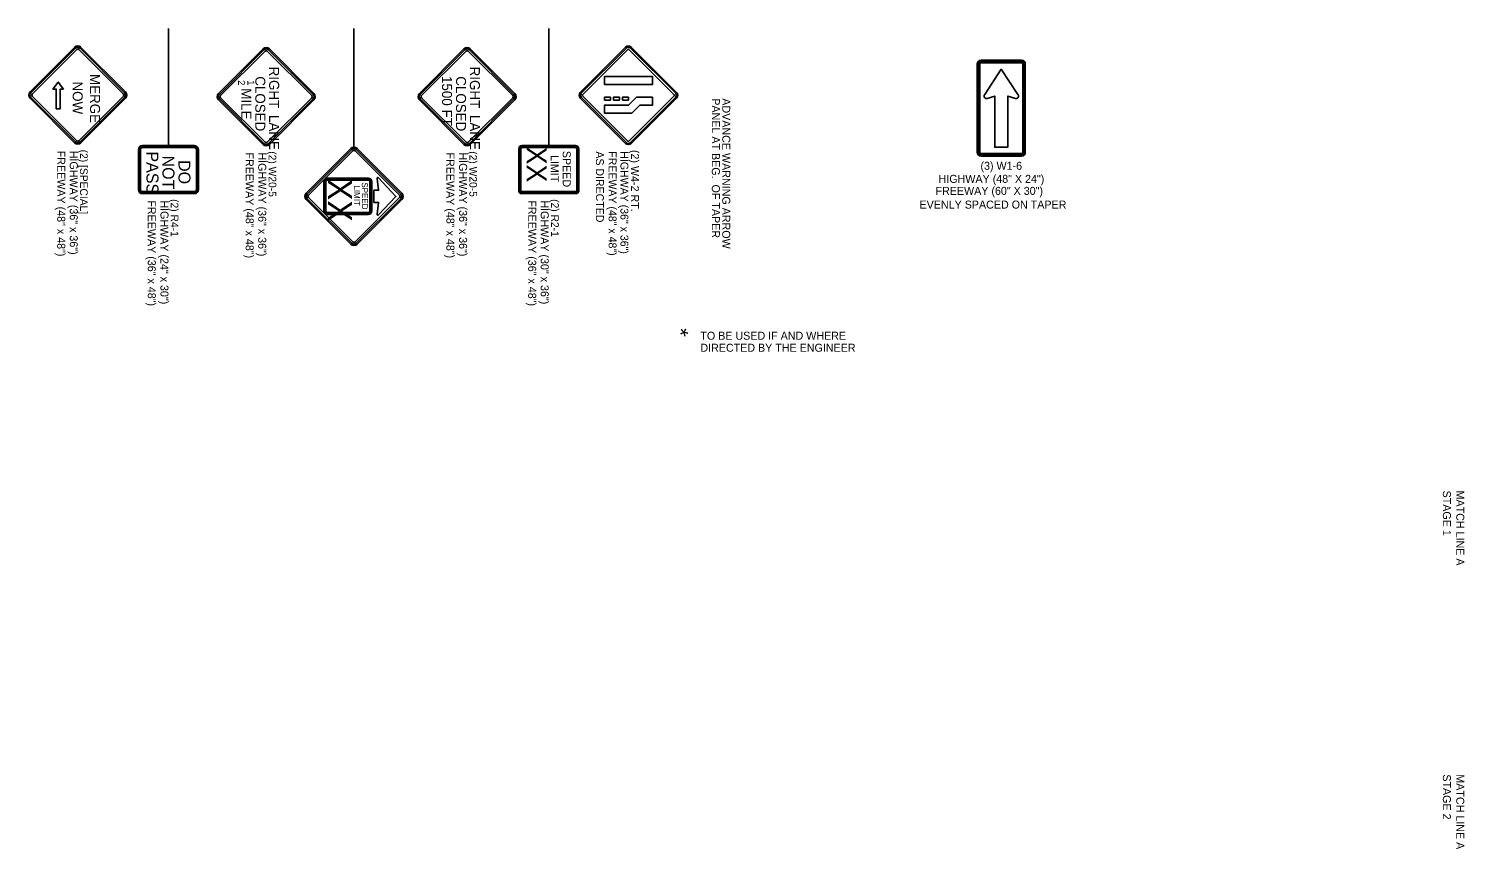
# Model space of a CAD drawing. Extents: x 1930579 to 1937521, y 596183 to 597566.
# Drawn here: x 1934037 to 1935114, y 596519 to 597134 of the extents above; entities that cross this region are included whole.
import ezdxf

# ---------------------------------------------------------------- set-up
doc = ezdxf.new("R2010")
doc.units = 0
for name, color, linetype in [('Default', 7, 'Continuous'), ('P_TC_Signs_Permanent', 7, 'Continuous'), ('P_TC_Signs_Temporary', 7, 'Continuous'), ('R_Annotation', 7, 'Continuous'), ('R_MOT', 7, 'Continuous')]:
    doc.layers.add(name, color=color, linetype=linetype)

msp = doc.modelspace()

# ---------------------------------------------------------------- linework, layer by layer
at = {"layer": 'P_TC_Signs_Permanent'}
for p, q in [((1934450.9, 597086.1), (1934484.8, 597120.1)), ((1934748.5, 597107.5), (1934748.5, 597041.1)), ((1934749.2, 597107.5), (1934749.2, 597041.1)), ((1934750.4, 597107.5), (1934750.4, 597041.1)), ((1934781.7, 597110.3), (1934751.3, 597110.3)), ((1934781.7, 597109.5), (1934751.3, 597109.5)), ((1934781.7, 597108.4), (1934751.3, 597108.4)), ((1934782.6, 597041.1), (1934782.6, 597107.5)), ((1934783.7, 597041.1), (1934783.7, 597107.5)), ((1934784.5, 597041.1), (1934784.5, 597107.5)), ((1934504.9, 597092), (1934504.9, 597098)), ((1934484.8, 597047.9), (1934450.9, 597081.9)), ((1934523, 597081.9), (1934489, 597047.9)), ((1934119.6, 597043.2), (1934119.6, 597013.2)), ((1934120.2, 597043.2), (1934120.2, 597013.2)), ((1934121.1, 597043.2), (1934121.1, 597013.2)), ((1934161.6, 597046.2), (1934122.6, 597046.2)), ((1934161.6, 597045.6), (1934122.6, 597045.6)), ((1934161.6, 597044.7), (1934122.6, 597044.7)), ((1934163.1, 597013.2), (1934163.1, 597043.2)), ((1934164, 597013.2), (1934164, 597043.2)), ((1934164.6, 597013.2), (1934164.6, 597043.2)), ((1934278.8, 597044), (1934245.4, 597010.6)), ((1934279.5, 597043.3), (1934246.1, 597009.9)), ((1934316.3, 597009.9), (1934282.9, 597043.3)), ((1934317, 597010.6), (1934283.6, 597044)), ((1934404.7, 597043.9), (1934404.7, 597012.4)), ((1934405.3, 597043.9), (1934405.3, 597012.4)), ((1934406.2, 597043.9), (1934406.2, 597012.4)), ((1934447.5, 597046.2), (1934407, 597046.2)), ((1934447.5, 597045.6), (1934407, 597045.6)), ((1934447.5, 597044.7), (1934407, 597044.7)), ((1934448.2, 597012.4), (1934448.2, 597043.9)), ((1934449.2, 597012.4), (1934449.2, 597043.9)), ((1934449.7, 597012.4), (1934449.7, 597043.9)), ((1934280.4, 597042.4), (1934247, 597009)), ((1934315.4, 597009), (1934282, 597042.4)), ((1934751.3, 597040.2), (1934781.7, 597040.2)), ((1934751.3, 597039), (1934781.7, 597039)), ((1934751.3, 597038.3), (1934781.7, 597038.3)), ((1934261, 597021.7), (1934292.2, 597021.7)), ((1934122.6, 597011.7), (1934161.6, 597011.7)), ((1934122.6, 597010.8), (1934161.6, 597010.8)), ((1934258.6, 596997.1), (1934258.6, 597019.3)), ((1934294.6, 597019.3), (1934294.6, 596997.1)), ((1934407, 597011.7), (1934447.5, 597011.7)), ((1934407, 597010.8), (1934447.5, 597010.8)), ((1934122.6, 597010.2), (1934161.6, 597010.2)), ((1934245.4, 597005.8), (1934278.8, 596972.4)), ((1934246.1, 597006.4), (1934279.5, 596973)), ((1934247, 597007.4), (1934280.4, 596974)), ((1934282, 596974), (1934315.4, 597007.4)), ((1934282.9, 596973), (1934316.3, 597006.4)), ((1934283.6, 596972.4), (1934317, 597005.8)), ((1934407, 597010.2), (1934447.5, 597010.2)), ((1934292.2, 596994.7), (1934261, 596994.7))]:
    msp.add_line(p, q, dxfattribs=at)
for points in [[(1934485.4, 597119.4), (1934451.5, 597085.5)], [(1934452.6, 597084.4), (1934486.5, 597118.4)], [(1934487.3, 597118.4), (1934521.3, 597084.4)], [(1934522.4, 597085.5), (1934488.4, 597119.4)], [(1934489, 597120.1), (1934506, 597103.1), (1934523, 597086.1)], [(1934778.9, 597084.5), (1934766.5, 597103.5), (1934754.1, 597084.5)], [(1934451.5, 597082.5), (1934485.4, 597048.6)], [(1934486.5, 597049.6), (1934452.6, 597083.6)], [(1934521.3, 597083.6), (1934487.3, 597049.6)], [(1934488.4, 597048.6), (1934522.4, 597082.5)], [(1934755.9, 597081.6), (1934761.6, 597083.3), (1934761.6, 597045), (1934771.4, 597045), (1934771.4, 597083.3), (1934777.1, 597081.6)], [(1934298.5, 597021.6), (1934299.7, 597012.7), (1934296.1, 597012.7), (1934296.1, 597003.7), (1934299.7, 597003.7), (1934298.5, 596994.8)], [(1934299.5, 596994.3), (1934312.6, 597008.2), (1934299.5, 597022.1)], [(1934259.2, 597019.3), (1934259.2, 596997.1)], [(1934260.1, 596997.1), (1934260.1, 597019.3)], [(1934292.2, 597021.1), (1934261, 597021.1)], [(1934261, 597020.2), (1934292.2, 597020.2)], [(1934293.1, 597019.3), (1934293.1, 597008.2), (1934293.1, 596997.1)], [(1934294, 596997.1), (1934294, 597008.2), (1934294, 597019.3)], [(1934292.2, 596996.2), (1934261, 596996.2)], [(1934261, 596995.3), (1934292.2, 596995.3)]]:
    msp.add_lwpolyline(points, dxfattribs=at)
for points in [[(1934468.9, 597092), (1934468.9, 597098), (1934504.9, 597098), (1934504.9, 597092)], [(1934468.9, 597080.4), (1934468.9, 597082.5), (1934473.4, 597082.5), (1934473.4, 597080.4)], [(1934468.9, 597070.5), (1934468.9, 597076.5), (1934486.9, 597076.5), (1934492.9, 597082.5), (1934504.9, 597082.5), (1934504.9, 597076.5), (1934495.4, 597076.5), (1934489.4, 597070.5)], [(1934475.7, 597080.4), (1934475.7, 597082.5), (1934480.2, 597082.5), (1934480.2, 597080.4)], [(1934482.4, 597080.4), (1934482.4, 597082.5), (1934486.9, 597082.5), (1934486.9, 597080.4)]]:
    msp.add_lwpolyline(points, close=True, dxfattribs=at)
for centre, radius, start, end in [((1934486.9, 597117.9), 3, 45, 135), ((1934486.9, 597117.9), 2.1, 45, 135), ((1934486.9, 597117.9), 0.6, 45, 135), ((1934751.3, 597107.5), 2.81, 90, 180), ((1934751.3, 597107.5), 2.06, 90, 180), ((1934751.3, 597107.5), 0.938, 90, 180), ((1934781.7, 597107.5), 2.81, 360, 90), ((1934781.7, 597107.5), 2.06, 360, 90), ((1934781.7, 597107.5), 0.938, 360, 90), ((1934453, 597084), 3, 135, 225), ((1934520.9, 597084), 3, 315, 45), ((1934453, 597084), 2.1, 135, 225), ((1934453, 597084), 0.6, 135, 225), ((1934520.9, 597084), 0.6, 315, 45), ((1934520.9, 597084), 2.1, 315, 45), ((1934755.4, 597083.3), 1.76, 146.5994, 285.9691), ((1934691.3, 597125.5), 75, 326.5994, 326.857), ((1934777.6, 597083.3), 1.8, 254.0309, 33.4755), ((1934841.7, 597125.6), 75, 213.2286, 213.4755), ((1934122.6, 597043.2), 3, 90, 180), ((1934122.6, 597043.2), 2.4, 90, 180), ((1934122.6, 597043.2), 1.5, 90, 180), ((1934161.6, 597043.2), 3, 360, 90), ((1934161.6, 597043.2), 2.4, 360, 90), ((1934161.6, 597043.2), 1.5, 360, 90), ((1934281.2, 597041.6), 3.38, 45, 135), ((1934281.2, 597041.6), 2.44, 45, 135), ((1934281.2, 597041.6), 1.13, 45, 135), ((1934407, 597043.9), 2.25, 90, 180), ((1934407, 597043.9), 1.69, 90, 180), ((1934407, 597043.9), 0.75, 90, 180), ((1934447.5, 597043.9), 2.25, 360, 90), ((1934447.5, 597043.9), 1.69, 360, 90), ((1934447.5, 597043.9), 0.75, 360, 90), ((1934486.9, 597050), 3, 225, 315), ((1934486.9, 597050), 2.1, 225, 315), ((1934486.9, 597050), 0.6, 225, 315), ((1934751.3, 597041.1), 2.81, 180, 270), ((1934751.3, 597041.1), 2.06, 180, 270), ((1934751.3, 597041.1), 0.937, 180, 270), ((1934781.7, 597041.1), 2.81, 270, 360), ((1934781.7, 597041.1), 2.06, 270, 360), ((1934781.7, 597041.1), 0.938, 270, 360), ((1934261, 597019.3), 2.4, 90, 180), ((1934292.2, 597019.3), 2.4, 0, 90), ((1934299.1, 597021.7), 0.563, 43.3117, 187.125), ((1934122.6, 597013.2), 3, 180, 270), ((1934122.6, 597013.2), 2.4, 180, 270), ((1934122.6, 597013.2), 1.5, 180, 270), ((1934161.6, 597013.2), 3, 270, 360), ((1934161.6, 597013.2), 2.4, 270, 360), ((1934161.6, 597013.2), 1.5, 270, 360), ((1934247.8, 597008.2), 3.38, 135, 225), ((1934261, 597019.3), 1.8, 90, 180), ((1934261, 597019.3), 0.9, 90, 180), ((1934292.2, 597019.3), 1.8, 0, 90), ((1934292.2, 597019.3), 0.9, 0, 90), ((1934314.6, 597008.2), 3.38, 315, 45), ((1934407, 597012.4), 2.25, 180, 270), ((1934407, 597012.4), 1.69, 180, 270), ((1934407, 597012.4), 0.75, 180, 270), ((1934447.5, 597012.4), 2.25, 270, 360), ((1934447.5, 597012.4), 1.69, 270, 360), ((1934447.5, 597012.4), 0.75, 270, 360), ((1934247.8, 597008.2), 2.44, 135, 225), ((1934247.8, 597008.2), 1.13, 135, 225), ((1934314.6, 597008.2), 1.13, 315, 45), ((1934314.6, 597008.2), 2.44, 315, 45), ((1934261, 596997.1), 2.4, 180, 270), ((1934261, 596997.1), 1.8, 180, 270), ((1934261, 596997.1), 0.9, 180, 270), ((1934292.2, 596997.1), 2.4, 270, 0), ((1934292.2, 596997.1), 1.8, 270, 0), ((1934292.2, 596997.1), 0.9, 270, 0), ((1934299.1, 596994.7), 0.563, 172.875, 316.6883), ((1934281.2, 596974.8), 3.38, 225, 315), ((1934281.2, 596974.8), 2.44, 225, 315), ((1934281.2, 596974.8), 1.13, 225, 315)]:
    msp.add_arc(centre, radius, start, end, dxfattribs=at)
at = {"layer": 'P_TC_Signs_Temporary'}
for p, q in [((1934038.3, 597086.5), (1934071.7, 597119.9)), ((1934039, 597085.9), (1934072.4, 597119.3)), ((1934039.9, 597084.9), (1934073.3, 597118.4)), ((1934074.9, 597118.4), (1934108.3, 597084.9)), ((1934075.8, 597119.3), (1934109.2, 597085.9)), ((1934076.5, 597119.9), (1934109.9, 597086.5)), ((1934179.6, 597085.3), (1934213, 597118.7)), ((1934180.3, 597084.6), (1934213.7, 597118)), ((1934217.1, 597118), (1934250.6, 597084.6)), ((1934217.8, 597118.7), (1934251.2, 597085.3)), ((1934330.2, 597085.3), (1934363.6, 597118.7)), ((1934330.9, 597084.6), (1934364.3, 597118)), ((1934367.7, 597118), (1934401.1, 597084.6)), ((1934368.4, 597118.7), (1934401.8, 597085.3)), ((1934181.2, 597083.7), (1934214.6, 597117.1)), ((1934216.2, 597117.1), (1934249.6, 597083.7)), ((1934331.8, 597083.7), (1934365.2, 597117.1)), ((1934366.8, 597117.1), (1934400.2, 597083.7)), ((1934071.7, 597048.3), (1934038.3, 597081.8)), ((1934072.4, 597049), (1934039, 597082.4)), ((1934073.3, 597049.9), (1934039.9, 597083.3)), ((1934108.3, 597083.3), (1934074.9, 597049.9)), ((1934109.2, 597082.4), (1934075.8, 597049)), ((1934109.9, 597081.8), (1934076.5, 597048.3)), ((1934213, 597047.1), (1934179.6, 597080.5)), ((1934213.7, 597047.8), (1934180.3, 597081.2)), ((1934214.6, 597048.7), (1934181.2, 597082.1)), ((1934249.6, 597082.1), (1934216.2, 597048.7)), ((1934250.6, 597081.2), (1934217.1, 597047.8)), ((1934251.2, 597080.5), (1934217.8, 597047.1)), ((1934363.6, 597047.1), (1934330.2, 597080.5)), ((1934364.3, 597047.8), (1934330.9, 597081.2)), ((1934365.2, 597048.7), (1934331.8, 597082.1)), ((1934400.2, 597082.1), (1934366.8, 597048.7)), ((1934401.1, 597081.2), (1934367.7, 597047.8)), ((1934401.8, 597080.5), (1934368.4, 597047.1))]:
    msp.add_line(p, q, dxfattribs=at)
for centre, radius, start, end in [((1934074.1, 597117.6), 3.37, 45, 135), ((1934074.1, 597117.6), 2.44, 45, 135), ((1934074.1, 597117.6), 1.12, 45, 135), ((1934215.4, 597116.3), 3.37, 45, 135), ((1934215.4, 597116.3), 2.44, 45, 135), ((1934366, 597116.3), 3.37, 45, 135), ((1934366, 597116.3), 2.44, 45, 135), ((1934215.4, 597116.3), 1.12, 45, 135), ((1934366, 597116.3), 1.12, 45, 135), ((1934040.7, 597084.1), 3.37, 135, 225), ((1934040.7, 597084.1), 2.44, 135, 225), ((1934107.5, 597084.1), 2.44, 315, 45), ((1934107.5, 597084.1), 3.38, 315, 45), ((1934040.7, 597084.1), 1.13, 135, 225), ((1934107.5, 597084.1), 1.13, 315, 45), ((1934182, 597082.9), 3.37, 135, 225), ((1934182, 597082.9), 2.44, 135, 225), ((1934182, 597082.9), 1.13, 135, 225), ((1934248.8, 597082.9), 1.13, 315, 45), ((1934248.8, 597082.9), 2.44, 315, 45), ((1934248.8, 597082.9), 3.38, 315, 45), ((1934332.6, 597082.9), 3.37, 135, 225), ((1934332.6, 597082.9), 2.44, 135, 225), ((1934332.6, 597082.9), 1.13, 135, 225), ((1934399.4, 597082.9), 1.13, 315, 45), ((1934399.4, 597082.9), 2.44, 315, 45), ((1934399.4, 597082.9), 3.38, 315, 45), ((1934074.1, 597050.7), 3.38, 225, 315), ((1934074.1, 597050.7), 2.44, 225, 315), ((1934074.1, 597050.7), 1.12, 225, 315), ((1934215.4, 597049.5), 3.38, 225, 315), ((1934215.4, 597049.5), 2.44, 225, 315), ((1934215.4, 597049.5), 1.12, 225, 315), ((1934366, 597049.5), 3.38, 225, 315), ((1934366, 597049.5), 2.44, 225, 315), ((1934366, 597049.5), 1.12, 225, 315)]:
    msp.add_arc(centre, radius, start, end, dxfattribs=at)
at = {"layer": 'R_Annotation'}
for p, q in [((1934142.1, 597133.9), (1934142.1, 597046.2)), ((1934281.2, 597133.9), (1934281.2, 597045)), ((1934427.2, 597133.9), (1934427.2, 597046.2))]:
    msp.add_line(p, q, dxfattribs=at)
at = {"layer": 'R_MOT'}
msp.add_lwpolyline([(1934063.5, 597088.6), (1934059.5, 597093.8), (1934055.5, 597088.6), (1934058, 597088.6), (1934058, 597073.9), (1934061, 597073.9), (1934061, 597088.6)], close=True, dxfattribs=at)

# ---------------------------------------------------------------- texts
at = {"layer": 'Default'}
for s, p in [('STAGE 1', (1935097.6, 596787.6)), ('MATCH LINE A ', (1935107.6, 596787.6)), ('STAGE 2', (1935097.6, 596574.9)), ('MATCH LINE A ', (1935107.6, 596574.9))]:
    msp.add_text(s, height=6, rotation=270, dxfattribs=at).set_placement(p)
at = {"layer": 'P_TC_Signs_Permanent'}
for s, height, rotation, p in [('XX', 15, 270, (1934410.7, 597045.5)), ('PASS', 9, 270, (1934125.6, 597041.9)), ('NOT', 9, 269.9596, (1934137.6, 597038.8)), ('DO', 9, 270, (1934149.6, 597035.4)), ('LIMIT', 6, 270, (1934428.7, 597039.2)), ('SPEED', 6, 270, (1934437.7, 597042.3)), ('XX', 18, 270, (1934261.6, 597021.3)), ('LIMIT', 4.5, 270, (1934281.1, 597016.4)), ('SPEED', 4.5, 270, (1934287.1, 597018.7))]:
    msp.add_text(s, height=height, rotation=rotation, dxfattribs=at).set_placement(p)
at = {"layer": 'P_TC_Signs_Temporary'}
for s, height, p in [('MERGE', 7.5, (1934083.3, 597099.9)), ('CLOSED', 7.5, (1934207.2, 597098.2)), ('RIGHT\u2002LANE', 7.5, (1934217.6, 597105.4)), ('1500 FT', 7.5, (1934347.2, 597098.4)), ('CLOSED', 7.5, (1934357.7, 597098.2)), ('RIGHT\u2002LANE', 7.5, (1934368.1, 597105.4)), ('NOW', 7.5, (1934070.3, 597094.3)), ('2', 5.25, (1934194.3, 597095.3)), (' MILE', 7.5, (1934196.7, 597092)), ('1', 5.25, (1934201.3, 597095.3))]:
    msp.add_text(s, height=height, rotation=270, dxfattribs=at).set_placement(p)
at = {"layer": 'R_Annotation'}
for s, height, rotation, p in [('PANEL AT BEG.  OF TAPER', 6, 270, (1934549.5, 597081.7)), ('ADVANCE WARNING ARROW', 6, 270, (1934557.3, 597081.7)), ('(2) [SPECIAL]', 5.76, 270, (1934075.8, 597043.2)), ('FREEWAY (48" x 48")', 6, 270, (1934058.7, 597042.4)), ('HIGHWAY (36" x 36")', 6, 270, (1934068.1, 597042.4)), ('FREEWAY (48" x 48")', 6, 270, (1934200, 597041.1)), ('HIGHWAY (36" x 36")', 6, 270, (1934209.4, 597041.1)), ('(2) W20-5', 5.76, 270, (1934217.2, 597042)), ('FREEWAY (48" x 48")', 6, 270, (1934350.5, 597041.1)), ('HIGHWAY (36" x 36")', 6, 270, (1934360, 597041.1)), ('(2) W20-5', 5.76, 270, (1934367.7, 597042)), ('AS DIRECTED ', 5.925, 270, (1934462.6, 597041.9)), ('FREEWAY (48" x 48")', 5.925, 270, (1934472.1, 597042)), ('HIGHWAY (36" x 36")', 5.925, 270, (1934481, 597042)), ('(2) W4-2 RT.', 6, 270, (1934488.9, 597043)), ('(3) W1-6', 6, 0.0075, (1934750.9, 597028.1)), ('HIGHWAY (48" X 24")', 6, 0.0075, (1934719.5, 597018.3)), ('FREEWAY (60" X 30")', 6, 0.0075, (1934717.2, 597009.3)), ('FREEWAY (36" x 48")', 6, 270, (1934126.6, 597005.2)), ('HIGHWAY (24" x 30")', 6, 270, (1934136.1, 597005.2)), ('(2) R4-1', 5.76, 270, (1934143.8, 597006.1)), ('FREEWAY (36" x 48")', 6, 270, (1934411.8, 597005.2)), ('HIGHWAY (30" x 36")', 6, 270, (1934421.2, 597005.2)), ('(2) R2-1', 5.76, 270, (1934429, 597006.1)), ('EVENLY SPACED ON TAPER', 6, 0.0075, (1934705.2, 596999)), ('*', 12, 45, (1934532.7, 596897.8)), ('TO BE USED IF AND WHERE', 6, 360, (1934540.9, 596900.7)), ('DIRECTED BY THE ENGINEER', 6, 360, (1934540.9, 596891.7))]:
    msp.add_text(s, height=height, rotation=rotation, dxfattribs=at).set_placement(p)

doc.saveas('drawing.dxf')
